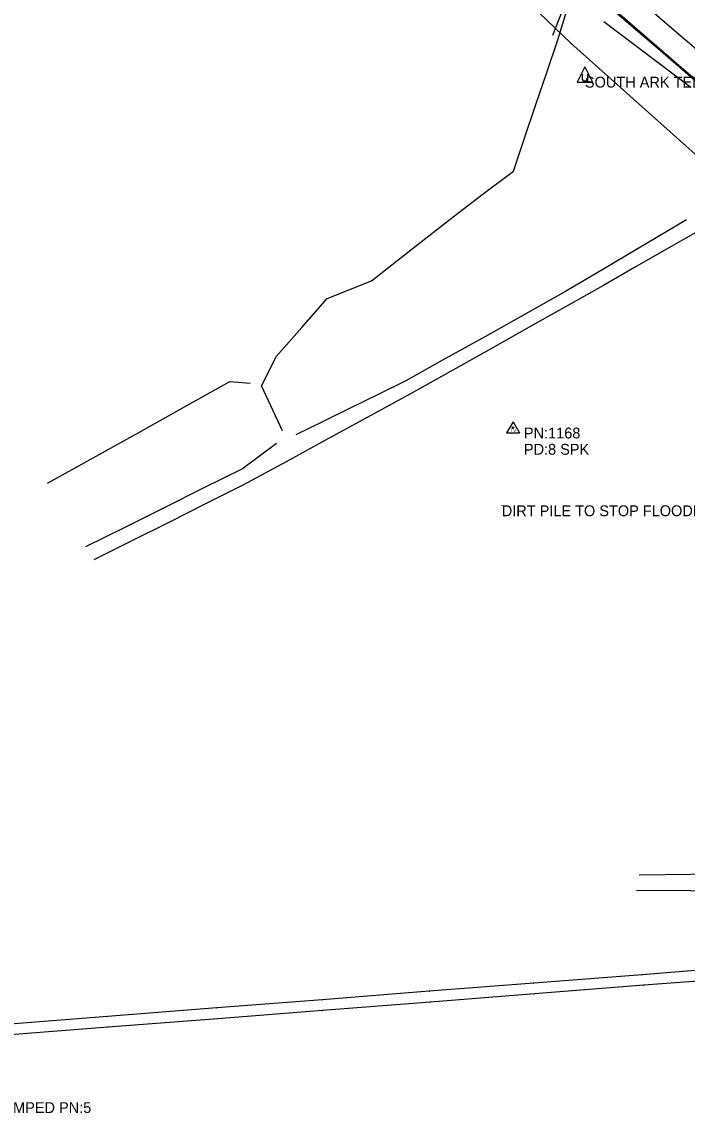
# Model space of a CAD drawing. Extents: x 878399 to 889864, y 1564003 to 1567413.
# Drawn here: x 884002 to 884308, y 1565379 to 1565882 of the extents above; entities that cross this region are included whole.
import ezdxf

# ---------------------------------------------------------------- set-up
doc = ezdxf.new("R2010")
doc.units = 0
for name, color, linetype in [('S_DITCHLINE', 7, 'Continuous'), ('S_EDGE_PAVEMENT', 7, 'Continuous'), ('S_FIBER_OPTIC_CABLE', 7, 'Continuous'), ('S_MSC_PT_SYM', 7, 'Continuous'), ('S_PAVEMENT_CROWN', 7, 'Continuous'), ('S_PRIMARY_CTL_ANNOT', 7, 'Continuous'), ('S_RAILROAD', 7, 'Continuous'), ('S_SECONDARY_CTL', 7, 'Continuous'), ('S_SECONDARY_CTL_ANNOT', 7, 'Continuous'), ('S_SHOULDER', 7, 'Continuous'), ('S_SURVEY_TEXT_ANNOT', 7, 'Continuous'), ('S_UTILITY_POLE', 7, 'Continuous'), ('S_UTILITY_POLE_ANNOT', 7, 'Continuous'), ('S_UTL_PT_SYM', 7, 'Continuous')]:
    doc.layers.add(name, color=color, linetype=linetype)

msp = doc.modelspace()

# ---------------------------------------------------------------- linework, layer by layer
at = {"layer": 'S_DITCHLINE'}
for points in [[(884121.95, 1565693.58), (884112.29, 1565714.29), (884119.13, 1565727.88), (884130.82, 1565741.22), (884142.51, 1565754.56), (884162.92, 1565762.71), (884181.72, 1565777.44), (884200.52, 1565792.16), (884214.44, 1565802.68), (884228.36, 1565813.2), (884233.47, 1565828.33), (884238.58, 1565843.46), (884243.69, 1565858.59), (884248.79, 1565873.71), (884254.05, 1565890.79)], [(884246.5, 1565875.89), (884252.61, 1565891.5)], [(884308.17, 1565790.82), (884294.15, 1565782.51), (884280.14, 1565774.2), (884266.13, 1565765.89), (884252.11, 1565757.58), (884233.77, 1565747.32), (884215.42, 1565737.06), (884197.08, 1565726.8), (884178.73, 1565716.54), (884166.05, 1565710.32), (884153.36, 1565704.11), (884140.67, 1565697.89), (884127.99, 1565691.67)], [(884313.57, 1565785.57), (884298.88, 1565777.18), (884284.19, 1565768.8), (884269.5, 1565760.41), (884254.81, 1565752.03), (884236.66, 1565741.86), (884218.52, 1565731.69), (884200.38, 1565721.52), (884182.24, 1565711.35), (884162.67, 1565700.67), (884143.1, 1565689.99), (884123.52, 1565679.31), (884103.95, 1565668.64), (884086.69, 1565660), (884069.42, 1565651.36), (884052.15, 1565642.72), (884034.89, 1565634.08)], [(884013.62, 1565669.45), (884034.64, 1565681.15), (884055.66, 1565692.85), (884076.67, 1565704.55), (884097.69, 1565716.25), (884106.99, 1565715.51)], [(884119.13, 1565687.66), (884103.51, 1565676.08), (884085.39, 1565667.07), (884067.28, 1565658.07), (884049.17, 1565649.07), (884031.06, 1565640.07)], [(884627.86, 1565496.72), (884604.94, 1565497.05), (884582.03, 1565497.38), (884559.11, 1565497.71), (884536.19, 1565498.04), (884516.04, 1565497.15), (884495.89, 1565496.27), (884475.74, 1565495.38), (884455.59, 1565494.49), (884437.16, 1565493.33), (884418.73, 1565492.17), (884400.3, 1565491.02), (884381.86, 1565489.86), (884357.97, 1565489.6), (884334.07, 1565489.34), (884310.17, 1565489.08), (884286.28, 1565488.82)], [(884625.97, 1565494.43), (884604.21, 1565493.18), (884582.45, 1565491.93), (884560.69, 1565490.67), (884538.93, 1565489.42), (884519.14, 1565488.86), (884499.35, 1565488.29), (884479.56, 1565487.72), (884459.77, 1565487.15), (884441.06, 1565485.61), (884422.36, 1565484.08), (884403.66, 1565482.54), (884384.95, 1565481.01), (884360, 1565481.18), (884335.05, 1565481.35), (884310.1, 1565481.52), (884285.15, 1565481.69)]]:
    msp.add_lwpolyline(points, dxfattribs=at)
at = {"layer": 'S_EDGE_PAVEMENT'}
for points in [[(884271.22, 1565890.15), (884282.58, 1565880.36), (884293.95, 1565870.57), (884305.36, 1565860.75), (884316.73, 1565850.97)], [(884271.66, 1565890.41), (884283.02, 1565880.62), (884294.39, 1565870.84), (884305.8, 1565861.01), (884317.17, 1565851.23)]]:
    msp.add_lwpolyline(points, dxfattribs=at)
at = {"layer": 'S_FIBER_OPTIC_CABLE'}
for p, q in [((884254.77, 1565872.1), (884217.64, 1565908)), ((884313.56, 1565819.73), (884254.77, 1565872.1))]:
    msp.add_line(p, q, dxfattribs=at)
at = {"layer": 'S_MSC_PT_SYM'}
for points in [[(884222.99, 1565659.21), (884222.99, 1565659.26), (884222.99, 1565659.21), (884222.94, 1565659.21), (884222.99, 1565659.21), (884222.99, 1565659.16), (884222.99, 1565659.21), (884223.04, 1565659.21)], [(884287.66, 1565442.92), (884287.66, 1565442.97), (884287.66, 1565442.92), (884287.61, 1565442.92), (884287.66, 1565442.92), (884287.66, 1565442.87), (884287.66, 1565442.92), (884287.71, 1565442.92)], [(884237.73, 1565439.03), (884237.73, 1565439.08), (884237.73, 1565439.03), (884237.68, 1565439.03), (884237.73, 1565439.03), (884237.73, 1565438.98), (884237.73, 1565439.03), (884237.78, 1565439.03)], [(884288.4, 1565438.05), (884288.4, 1565438.1), (884288.4, 1565438.05), (884288.35, 1565438.05), (884288.4, 1565438.05), (884288.4, 1565438), (884288.4, 1565438.05), (884288.45, 1565438.05)], [(884189.55, 1565435.28), (884189.55, 1565435.33), (884189.55, 1565435.28), (884189.5, 1565435.28), (884189.55, 1565435.28), (884189.55, 1565435.23), (884189.55, 1565435.28), (884189.6, 1565435.28)], [(884238.13, 1565434.11), (884238.13, 1565434.16), (884238.13, 1565434.11), (884238.08, 1565434.11), (884238.13, 1565434.11), (884238.13, 1565434.06), (884238.13, 1565434.11), (884238.18, 1565434.11)], [(884091.69, 1565427.65), (884091.69, 1565427.7), (884091.69, 1565427.65), (884091.64, 1565427.65), (884091.69, 1565427.65), (884091.69, 1565427.6), (884091.69, 1565427.65), (884091.74, 1565427.65)], [(884140.25, 1565431.42), (884140.25, 1565431.47), (884140.25, 1565431.42), (884140.2, 1565431.42), (884140.25, 1565431.42), (884140.25, 1565431.37), (884140.25, 1565431.42), (884140.3, 1565431.42)], [(884190.08, 1565430.35), (884190.08, 1565430.4), (884190.08, 1565430.35), (884190.03, 1565430.35), (884190.08, 1565430.35), (884190.08, 1565430.3), (884190.08, 1565430.35), (884190.13, 1565430.35)], [(884041.29, 1565423.7), (884041.29, 1565423.75), (884041.29, 1565423.7), (884041.24, 1565423.7), (884041.29, 1565423.7), (884041.29, 1565423.65), (884041.29, 1565423.7), (884041.34, 1565423.7)], [(884092.08, 1565422.67), (884092.08, 1565422.72), (884092.08, 1565422.67), (884092.03, 1565422.67), (884092.08, 1565422.67), (884092.08, 1565422.62), (884092.08, 1565422.67), (884092.13, 1565422.67)], [(884140.27, 1565426.41), (884140.27, 1565426.46), (884140.27, 1565426.41), (884140.22, 1565426.41), (884140.27, 1565426.41), (884140.27, 1565426.36), (884140.27, 1565426.41), (884140.32, 1565426.41)], [(884041.49, 1565418.76), (884041.49, 1565418.81), (884041.49, 1565418.76), (884041.44, 1565418.76), (884041.49, 1565418.76), (884041.49, 1565418.71), (884041.49, 1565418.76), (884041.54, 1565418.76)]]:
    msp.add_lwpolyline(points, dxfattribs=at)
at = {"layer": 'S_PAVEMENT_CROWN'}
msp.add_lwpolyline([(884290, 1565888.94), (884301.35, 1565879.14), (884312.72, 1565869.34)], dxfattribs=at)
at = {"layer": 'S_RAILROAD'}
for p, q in [((884336.64, 1565446.73), (884287.66, 1565442.92)), ((884287.66, 1565442.92), (884237.73, 1565439.03)), ((884337, 1565441.81), (884288.4, 1565438.05)), ((884237.73, 1565439.03), (884189.55, 1565435.28)), ((884288.4, 1565438.05), (884238.13, 1565434.11)), ((884189.55, 1565435.28), (884140.25, 1565431.42)), ((884238.13, 1565434.11), (884190.08, 1565430.35)), ((884091.69, 1565427.65), (884041.29, 1565423.7)), ((884140.25, 1565431.42), (884091.69, 1565427.65)), ((884190.08, 1565430.35), (884140.27, 1565426.41)), ((884041.29, 1565423.7), (883989.28, 1565419.62)), ((884092.08, 1565422.67), (884041.49, 1565418.76)), ((884140.27, 1565426.41), (884092.08, 1565422.67)), ((884041.49, 1565418.76), (883989.77, 1565414.71))]:
    msp.add_line(p, q, dxfattribs=at)
at = {"layer": 'S_SECONDARY_CTL'}
for p, q in [((884228.19, 1565697.64), (884225.18, 1565692.68)), ((884228.19, 1565697.64), (884231.14, 1565692.68)), ((884225.18, 1565692.68), (884231.14, 1565692.68))]:
    msp.add_line(p, q, dxfattribs=at)
for radius in [0.311, 0.183, 0.103]:
    msp.add_circle((884228.19, 1565695.03), radius, dxfattribs=at)
at = {"layer": 'S_SHOULDER'}
msp.add_lwpolyline([(884270.03, 1565882.19), (884310.06, 1565851.92)], dxfattribs=at)
at = {"layer": 'S_UTILITY_POLE'}
for p, q in [((884261.32, 1565861.24), (884257.79, 1565854.15)), ((884261.32, 1565861.24), (884264.81, 1565854.15)), ((884257.79, 1565854.15), (884264.81, 1565854.15)), ((884260.12, 1565855.39), (884260.12, 1565857.83)), ((884260.74, 1565854.73), (884260.12, 1565855.39)), ((884261.94, 1565854.73), (884260.74, 1565854.73)), ((884262.48, 1565855.39), (884261.94, 1565854.73)), ((884262.48, 1565857.83), (884262.48, 1565855.39))]:
    msp.add_line(p, q, dxfattribs=at)
at = {"layer": 'S_UTL_PT_SYM'}
msp.add_lwpolyline([(884254.77, 1565872.1), (884254.77, 1565872.15), (884254.77, 1565872.1), (884254.72, 1565872.1), (884254.77, 1565872.1), (884254.77, 1565872.05), (884254.77, 1565872.1), (884254.82, 1565872.1)], dxfattribs=at)

# ---------------------------------------------------------------- texts
at = {"layer": 'S_PRIMARY_CTL_ANNOT'}
msp.add_text('PD:ARDOT STD. MON. STAMPED PN:5', height=5, dxfattribs=at).set_placement((883911.89, 1565379.2))
at = {"layer": 'S_SECONDARY_CTL'}
msp.add_text('TV', height=1.5, rotation=360, dxfattribs=at).set_placement((884226.99, 1565693.01))
at = {"layer": 'S_SECONDARY_CTL_ANNOT'}
for s, p in [('PN:1168', (884233.19, 1565690.03)), ('PD:8 SPK', (884233.19, 1565682.53))]:
    msp.add_text(s, height=5, dxfattribs=at).set_placement(p)
at = {"layer": 'S_SURVEY_TEXT_ANNOT'}
msp.add_text('DIRT PILE TO STOP FLOODEN', height=5, dxfattribs=at).set_placement((884222.99, 1565654.21))
at = {"layer": 'S_UTILITY_POLE_ANNOT'}
msp.add_text('SOUTH ARK TELE TY:FOC', height=5, dxfattribs=at).set_placement((884261.32, 1565851.71))

doc.saveas('drawing.dxf')
